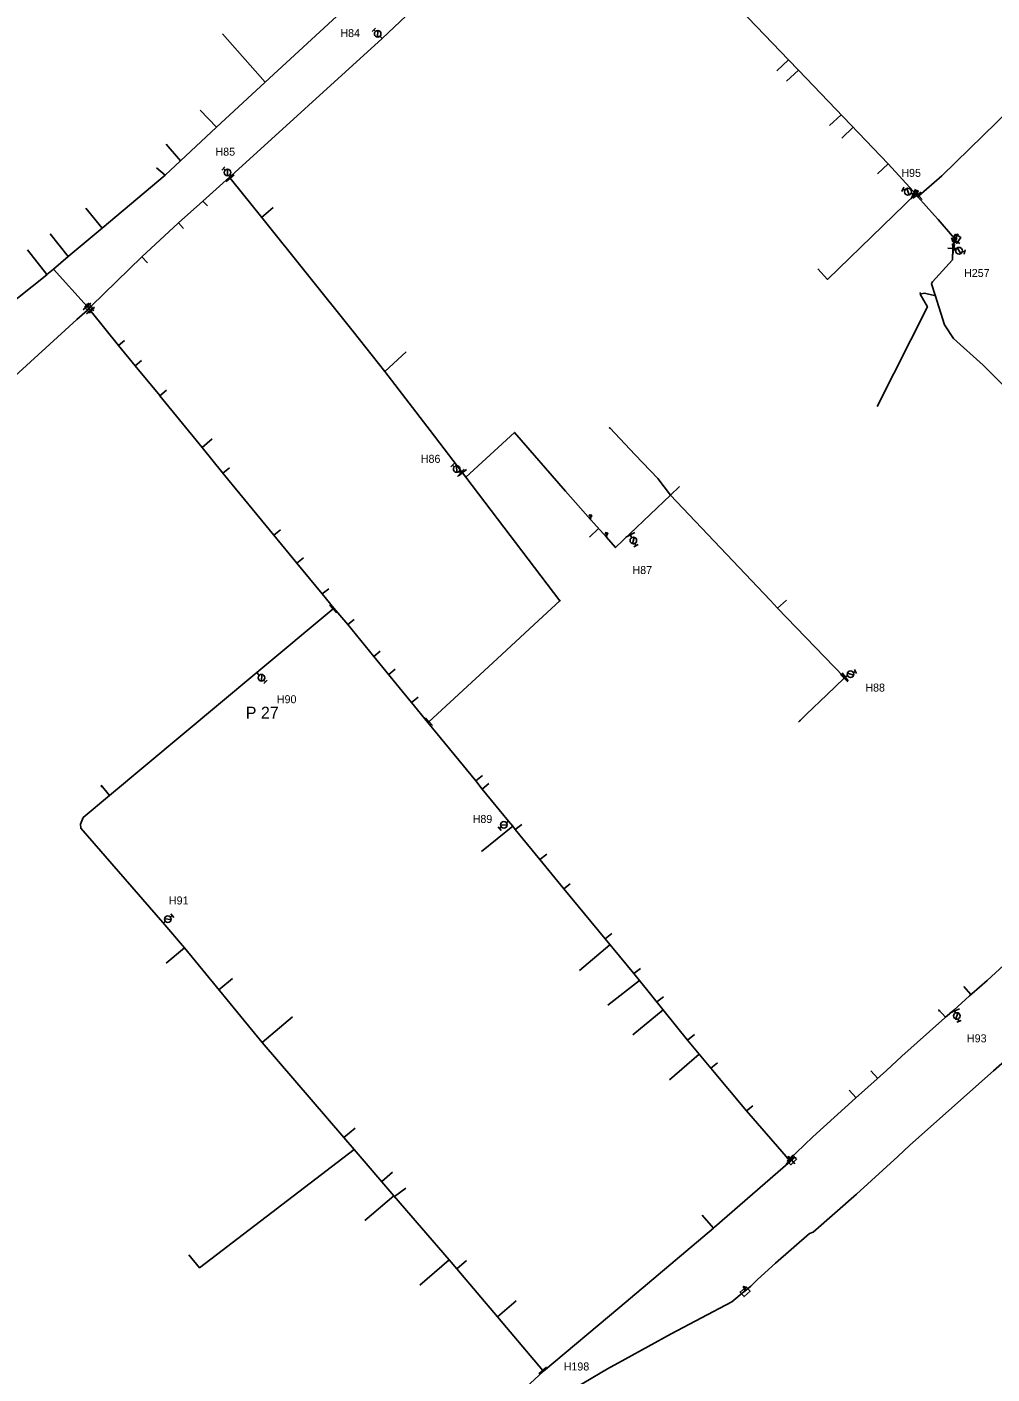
# Model space of a CAD drawing. Extents: x -548873 to -538270, y -1201997 to -1192514.
# Drawn here: x -544932.6 to -544691.4, y -1193789.4 to -1193452.8 of the extents above; entities that cross this region are included whole.
import ezdxf

# ---------------------------------------------------------------- set-up
doc = ezdxf.new("R2010")
doc.units = 0
for name, color, linetype in [('KN_HRAN_STÁTNÍ', 7, 'Continuous'), ('KN_PARC_Č', 7, 'Continuous'), ('KN_VKP_HRAN_SPORNÁ', 7, 'Continuous'), ('PK_PARC_Čv', 7, 'Continuous'), ('Vrstva 29', 7, 'Continuous'), ('Vrstva 39', 7, 'Continuous')]:
    doc.layers.add(name, color=color, linetype=linetype)

# ---------------------------------------------------------------- blocks, each defined once
blk = doc.blocks.new('160')
at = {"layer": 'KN_HRAN_STÁTNÍ'}
blk.add_circle((0, 0), 0.0458, dxfattribs=at)
blk = doc.blocks.new('147')
at = {"layer": 'KN_HRAN_STÁTNÍ'}
blk.add_line((0, 1.27), (0, -1.27), dxfattribs=at)
blk = doc.blocks.new('133')
at = {"layer": 'KN_HRAN_STÁTNÍ'}
for p, q in [((0.28, 0), (0, 0)), ((0.54, 0.58), (1.7, -0.58)), ((1.94, 0), (2.52, 0)), ((2.52, 0.58), (2.52, -0.58))]:
    blk.add_line(p, q, dxfattribs=at)
blk.add_circle((1.11, 0), 0.825, dxfattribs=at)
blk = doc.blocks.new('150')
at = {"layer": 'KN_HRAN_STÁTNÍ'}
blk.add_line((0, 1.27), (0, -1.27), dxfattribs=at)
blk = doc.blocks.new('123')
at = {"layer": 'KN_HRAN_STÁTNÍ'}
for p, q in [((-0.26, 0.96), (0.26, 0.96)), ((-0.19, 1.13), (0.19, 0.79)), ((-0.19, 0.79), (0, 0.96)), ((0, 1.22), (0, 0.96)), ((0, 0.96), (0.19, 1.13)), ((0, 0.96), (0, 0))]:
    blk.add_line(p, q, dxfattribs=at)
blk = doc.blocks.new('128')
at = {"layer": 'KN_HRAN_STÁTNÍ'}
for p, q in [((-0.19, 1.06), (-0.43, 1.15)), ((-0.36, 0.84), (-0.19, 1.06)), ((-0.19, 1.06), (-0.02, 1.25)), ((-0.19, 1.06), (0, 0)), ((0.05, 0.95), (-0.19, 1.06)), ((-0.1, 1), (0.41, 0.91)), ((-0.07, 0.82), (0.17, 0.96)), ((0.17, 0.96), (-0.02, 1.13)), ((0.17, 0.96), (0, 0)), ((0.19, 1.21), (0.17, 0.96)), ((0.17, 0.96), (0.38, 1.08)), ((0.36, 0.77), (0.17, 0.96))]:
    blk.add_line(p, q, dxfattribs=at)

msp = doc.modelspace()

# ---------------------------------------------------------------- linework, layer by layer
at = {"layer": 'KN_PARC_Č'}
for points in [[(-544873.033, -1193466.619), (-544883.731, -1193454.497)], [(-544742.227, -1193461.065), (-544745.196, -1193463.789)], [(-544739.778, -1193463.618), (-544742.725, -1193466.361)], [(-544885.192, -1193477.869), (-544889.335, -1193473.618)], [(-544729.091, -1193474.746), (-544732.034, -1193477.424)], [(-544726.1, -1193477.86), (-544728.929, -1193480.577)], [(-544894.197, -1193486.235), (-544897.8, -1193482.11)], [(-544898.064, -1193489.828), (-544900.243, -1193487.976)], [(-544717.339, -1193486.981), (-544720.032, -1193489.471)], [(-544888.647, -1193496.321), (-544887.5, -1193497.53)], [(-544710.407, -1193494.519), (-544732.514, -1193515.885), (-544734.919, -1193513.238)], [(-544913.832, -1193503.099), (-544917.852, -1193498.09)], [(-544873.952, -1193500.379), (-544871.054, -1193497.935)], [(-544894.752, -1193501.782), (-544893.436, -1193503.148)], [(-544922.268, -1193510.197), (-544926.82, -1193504.522)], [(-544927.61, -1193514.691), (-544932.433, -1193508.509)], [(-544903.885, -1193510.255), (-544902.488, -1193511.732)], [(-544709.33, -1193519.55), (-544707.512, -1193522.725), (-544720.054, -1193547.602)], [(-544705.585, -1193519.832), (-544705.74, -1193519.88), (-544707.62, -1193519.48), (-544708.22, -1193519.35), (-544709.33, -1193519.55)], [(-544709.228, -1193519.532), (-544709.322, -1193519.134)], [(-544909.698, -1193532.358), (-544908.188, -1193531.174)], [(-544905.517, -1193537.473), (-544903.967, -1193536.169)], [(-544843.108, -1193538.914), (-544837.816, -1193533.992)], [(-544899.413, -1193544.942), (-544897.761, -1193543.581)], [(-544888.849, -1193557.868), (-544886.29, -1193555.721)], [(-544883.617, -1193564.271), (-544881.968, -1193562.946)], [(-544771.738, -1193569.762), (-544769.5, -1193567.65)], [(-544870.88, -1193579.796), (-544869.263, -1193578.46)], [(-544789.711, -1193578.09), (-544791.978, -1193580.241)], [(-544865.131, -1193586.804), (-544863.448, -1193585.479)], [(-544858.846, -1193594.464), (-544857.155, -1193593.169)], [(-544744.998, -1193597.978), (-544742.759, -1193595.984)], [(-544852.38, -1193602.073), (-544850.854, -1193600.827)], [(-544845.888, -1193610.063), (-544844.277, -1193608.781)], [(-544842.178, -1193614.626), (-544840.545, -1193613.298)], [(-544836.52, -1193621.593), (-544834.816, -1193620.23)], [(-544739.399, -1193626.149), (-544739.759, -1193626.496)], [(-544820.435, -1193641.185), (-544818.766, -1193639.836)], [(-544913.879, -1193642.507), (-544914.117, -1193642.691)], [(-544911.976, -1193644.837), (-544914.069, -1193642.275)], [(-544818.785, -1193643.205), (-544817.121, -1193641.843)], [(-544811.174, -1193652.518), (-544818.983, -1193658.775)], [(-544810.548, -1193653.281), (-544808.92, -1193652.054)], [(-544804.407, -1193660.773), (-544802.667, -1193659.443)], [(-544798.406, -1193668.095), (-544796.782, -1193666.903)], [(-544788.101, -1193680.666), (-544786.411, -1193679.28)], [(-544893.189, -1193682.912), (-544897.792, -1193686.739)], [(-544786.877, -1193682.134), (-544794.498, -1193688.515)], [(-544780.898, -1193689.308), (-544779.247, -1193687.998)], [(-544884.614, -1193693.379), (-544881.222, -1193690.515)], [(-544779.504, -1193691.04), (-544787.416, -1193697.165)], [(-544775.194, -1193696.376), (-544773.501, -1193695.099)], [(-544696.662, -1193694.566), (-544698.439, -1193692.575)], [(-544773.59, -1193698.363), (-544781.188, -1193704.621)], [(-544704.534, -1193698.512), (-544704.765, -1193698.703)], [(-544702.986, -1193700.221), (-544704.735, -1193698.289)], [(-544873.845, -1193706.525), (-544866.26, -1193700.154)], [(-544767.49, -1193705.915), (-544765.716, -1193704.49)], [(-544764.572, -1193709.412), (-544772.018, -1193715.812)], [(-544761.655, -1193712.908), (-544759.951, -1193711.581)], [(-544719.951, -1193715.483), (-544721.654, -1193713.596)], [(-544725.331, -1193720.353), (-544727.063, -1193718.452)], [(-544752.717, -1193723.614), (-544751.169, -1193722.334)], [(-544853.421, -1193730.247), (-544850.57, -1193727.951)], [(-544850.798, -1193733.293), (-544889.439, -1193762.797), (-544892.119, -1193759.553)], [(-544843.94, -1193741.259), (-544841.239, -1193738.946)], [(-544840.872, -1193744.822), (-544848.147, -1193751.016)], [(-544840.715, -1193745.004), (-544837.908, -1193742.918)], [(-544761.018, -1193752.882), (-544763.857, -1193749.62)], [(-544827.064, -1193760.838), (-544834.422, -1193767.118)], [(-544825.186, -1193763.054), (-544822.763, -1193761.008)], [(-544815.004, -1193775.064), (-544810.343, -1193771.023)]]:
    msp.add_lwpolyline(points, dxfattribs=at)
at = {"layer": 'KN_VKP_HRAN_SPORNÁ'}
for points in [[(-544925.975, -1193513.316), (-544922.268, -1193510.197), (-544913.832, -1193503.099), (-544898.092, -1193489.854), (-544898.064, -1193489.828), (-544894.197, -1193486.235), (-544885.192, -1193477.869), (-544873.034, -1193466.62), (-544842.561, -1193438.428), (-544812.835, -1193411.457), (-544812.726, -1193411.357), (-544800.327, -1193400.27), (-544799.558, -1193390.689), (-544799.344, -1193382.742), (-544799.63, -1193373.727)], [(-544618.32, -1193373.547), (-544618.82, -1193374.46), (-544619.09, -1193374.97), (-544620.49, -1193377.221), (-544637.21, -1193404.11), (-544643.44, -1193413.61), (-544645.44, -1193416.9), (-544646.687, -1193418.924), (-544662.3, -1193444.264), (-544665.07, -1193448.54), (-544670.89, -1193456.94), (-544680.37, -1193467.03), (-544684.479, -1193471.289), (-544686.79, -1193473.29), (-544703.94, -1193490), (-544709.66, -1193495.02)], [(-544793.743, -1193408.084), (-544778.557, -1193423.289), (-544776.054, -1193425.797), (-544750.274, -1193452.675), (-544742.226, -1193461.066), (-544739.778, -1193463.618), (-544717.339, -1193486.981), (-544710.13, -1193494.82)], [(-544881.976, -1193490.354), (-544881.575, -1193489.989), (-544843.851, -1193455.663), (-544831.902, -1193444.36), (-544830.172, -1193442.723), (-544830.065, -1193442.622), (-544823.294, -1193436.106)], [(-544916.82, -1193522.85), (-544916.573, -1193522.589), (-544903.885, -1193510.255), (-544894.775, -1193501.803), (-544894.752, -1193501.782), (-544888.647, -1193496.321), (-544881.976, -1193490.354)], [(-544881.976, -1193490.354), (-544881.788, -1193490.589)], [(-544881.788, -1193490.589), (-544881.479, -1193490.969), (-544873.919, -1193500.42), (-544851.103, -1193528.925), (-544843.108, -1193538.914), (-544831.823, -1193553.642), (-544823.738, -1193564.193)], [(-544710.13, -1193494.82), (-544709.904, -1193495.234)], [(-544709.904, -1193495.234), (-544709.66, -1193495.02)], [(-544709.904, -1193495.234), (-544709.89, -1193495.26), (-544705.72, -1193499.91), (-544704.841, -1193500.925), (-544701.231, -1193505.09), (-544700.53, -1193505.56)], [(-544700.52, -1193506.23), (-544700.847, -1193506.756), (-544701.16, -1193507.68), (-544701.17, -1193508.11)], [(-544700.53, -1193505.56), (-544700.23, -1193505.79)], [(-544700.23, -1193505.79), (-544700.52, -1193506.23)], [(-544701.17, -1193508.11), (-544701.29, -1193511), (-544706.24, -1193516.53), (-544706.43, -1193516.76), (-544706.47, -1193517), (-544705.585, -1193519.832), (-544703.27, -1193527.24), (-544700.98, -1193530.67), (-544693.61, -1193537.3), (-544680.95, -1193549.85)], [(-544954.743, -1193539), (-544954.598, -1193538.861), (-544938.639, -1193523.522), (-544927.643, -1193514.719), (-544927.61, -1193514.691), (-544925.975, -1193513.316)], [(-544917.576, -1193522.658), (-544925.975, -1193513.316)], [(-545065.203, -1193622.374), (-545052.13, -1193618.053), (-545037.812, -1193613.321), (-545003.877, -1193595.413), (-544988.151, -1193585.243), (-544974.889, -1193574.667), (-544966.191, -1193567.738), (-544949.232, -1193552.353), (-544920.109, -1193525.934), (-544917.513, -1193523.579), (-544917.12, -1193523.165)], [(-544917.12, -1193523.165), (-544917.576, -1193522.658)], [(-544917.12, -1193523.165), (-544916.82, -1193522.85)], [(-544917.12, -1193523.165), (-544916.721, -1193523.66)], [(-544916.721, -1193523.66), (-544916.532, -1193523.893), (-544909.698, -1193532.358), (-544905.519, -1193537.471), (-544899.432, -1193544.919), (-544899.413, -1193544.942), (-544888.849, -1193557.868), (-544883.618, -1193564.27), (-544870.878, -1193579.798), (-544865.131, -1193586.804), (-544858.848, -1193594.462), (-544855.904, -1193598.05)], [(-544822.922, -1193565.264), (-544810.763, -1193554.122), (-544798.028, -1193568.777), (-544791.72, -1193575.862)], [(-544786.918, -1193552.98), (-544780.541, -1193559.694), (-544774.94, -1193565.591), (-544771.738, -1193569.762)], [(-544823.738, -1193564.193), (-544822.922, -1193565.264)], [(-544799.371, -1193596.16), (-544822.922, -1193565.264)], [(-544771.738, -1193569.762), (-544781.914, -1193579.452), (-544785.505, -1193582.872), (-544787.702, -1193580.318)], [(-544771.738, -1193569.762), (-544746.821, -1193596.054), (-544744.998, -1193597.978), (-544730.897, -1193612.601), (-544728.226, -1193615.37), (-544728.347, -1193615.501)], [(-544791.72, -1193575.862), (-544787.702, -1193580.318)], [(-544832.141, -1193626.382), (-544815.095, -1193610.661), (-544805.826, -1193602.113), (-544799.371, -1193596.16)], [(-544856.096, -1193598.21), (-544875.146, -1193614.106), (-544884.752, -1193622.121), (-544911.976, -1193644.837), (-544918.588, -1193650.354), (-544919.246, -1193652.011), (-544919.103, -1193653.018), (-544898.673, -1193676.585), (-544893.189, -1193682.912), (-544873.845, -1193706.525), (-544853.421, -1193730.247), (-544850.798, -1193733.293), (-544840.872, -1193744.822), (-544827.064, -1193760.838), (-544825.186, -1193763.054), (-544815.004, -1193775.064), (-544803.674, -1193788.427)], [(-544855.904, -1193598.05), (-544856.096, -1193598.21)], [(-544855.904, -1193598.05), (-544852.378, -1193602.075), (-544845.888, -1193610.063), (-544838.816, -1193618.76), (-544836.521, -1193621.592), (-544832.362, -1193626.585)], [(-544728.347, -1193615.501), (-544732.677, -1193619.673), (-544737.703, -1193624.515), (-544739.197, -1193625.955), (-544739.399, -1193626.149)], [(-544832.362, -1193626.585), (-544832.141, -1193626.382)], [(-544832.362, -1193626.585), (-544820.437, -1193641.183), (-544818.784, -1193643.206), (-544812.245, -1193651.212), (-544811.176, -1193652.515), (-544810.548, -1193653.281), (-544804.406, -1193660.775), (-544798.404, -1193668.097), (-544788.099, -1193680.668), (-544780.898, -1193689.308), (-544779.504, -1193691.04), (-544767.49, -1193705.915), (-544761.655, -1193712.909), (-544752.717, -1193723.614), (-544742.205, -1193735.678), (-544741.982, -1193735.892)], [(-544686.327, -1193685.256), (-544692.588, -1193691.012), (-544696.41, -1193694.34), (-544696.99, -1193694.86), (-544700.93, -1193698.48), (-544702.96, -1193700.19), (-544703.14, -1193700.4), (-544713.921, -1193709.981), (-544717.76, -1193713.5), (-544725.46, -1193720.47), (-544736.16, -1193730.06), (-544740.35, -1193734.13), (-544740.89, -1193734.66), (-544741.6, -1193735.29)], [(-544753.19, -1193768.67), (-544752.199, -1193767.805), (-544751.7, -1193767.37), (-544749.99, -1193765.72), (-544745.49, -1193761.67), (-544736.98, -1193754.24), (-544736.11, -1193753.94), (-544725.23, -1193744.44), (-544714.9, -1193735.03), (-544711.92, -1193732.21), (-544691.02, -1193713.6), (-544680.67, -1193704.51), (-544679.98, -1193703.76), (-544679.27, -1193702.36), (-544678.562, -1193701.598)], [(-544741.6, -1193735.29), (-544741.24, -1193735.709)], [(-544741.466, -1193735.906), (-544741.24, -1193735.709)], [(-544741.24, -1193735.709), (-544741.051, -1193735.545)], [(-544741.73, -1193736.135), (-544760.729, -1193752.634), (-544760.93, -1193752.808), (-544761.018, -1193752.882), (-544784.43, -1193772.606), (-544803.48, -1193788.656)], [(-544741.982, -1193735.892), (-544741.73, -1193736.135)], [(-544741.73, -1193736.135), (-544741.466, -1193735.906)], [(-544818.462, -1193813.455), (-544817.886, -1193812.916), (-544795.275, -1193792.673), (-544787.528, -1193788.017), (-544783.111, -1193785.609), (-544771.592, -1193779.33), (-544756.443, -1193771.342), (-544753.287, -1193768.749), (-544753.19, -1193768.67)], [(-544803.48, -1193788.656), (-544832.8, -1193815.665), (-544842.513, -1193824.613), (-544845.213, -1193827.1), (-544854.51, -1193834.908), (-544866.558, -1193845.027), (-544867.737, -1193846.021), (-544882.866, -1193860.53), (-544900.46, -1193875.864)], [(-544803.674, -1193788.427), (-544803.48, -1193788.656)]]:
    msp.add_lwpolyline(points, dxfattribs=at)
at = {"layer": 'PK_PARC_Čv'}
for points in [[(-544843.851, -1193455.663), (-544844.168, -1193455.335)], [(-544881.576, -1193489.99), (-544881.66, -1193489.91)], [(-544710.651, -1193494.755), (-544710.749, -1193494.653), (-544711.06, -1193494.54), (-544711.33, -1193494.44)], [(-544700.46, -1193504.59), (-544699.2, -1193505.42), (-544700.14, -1193506.87), (-544701.4, -1193506.04), (-544700.46, -1193504.59)], [(-544701.182, -1193508.409), (-544700.96, -1193508.42), (-544700.71, -1193508.47)], [(-544918.195, -1193522.847), (-544917.255, -1193521.857), (-544915.94, -1193523.27), (-544916.88, -1193524.26), (-544918.195, -1193522.847)], [(-544823.735, -1193564.197), (-544823.934, -1193564.428), (-544824.38, -1193564.01)], [(-544781.914, -1193579.453), (-544781.78, -1193579.714), (-544781.549, -1193580.162)], [(-544875.146, -1193614.106), (-544874.71, -1193614.578)], [(-544728.468, -1193615.618), (-544728.055, -1193615.184), (-544727.742, -1193615.038)], [(-544812.243, -1193651.214), (-544812.547, -1193651.462)], [(-544898.563, -1193676.712), (-544898.22, -1193676.432)], [(-544700.859, -1193698.414), (-544700.69, -1193698.61), (-544700.59, -1193698.87)], [(-544742.55, -1193736.09), (-544741.14, -1193734.71), (-544740.22, -1193735.67), (-544741.63, -1193737.05), (-544742.55, -1193736.09)], [(-544752.845, -1193767.546), (-544751.855, -1193768.673), (-544753.357, -1193769.993), (-544754.347, -1193768.866), (-544752.845, -1193767.546)]]:
    msp.add_lwpolyline(points, dxfattribs=at)

# ---------------------------------------------------------------- block references
for name, p, xscale, yscale, rotation in [('133', (-544844.168, -1193455.335), 1.0000000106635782, 1.0000000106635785, 134.00000165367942), ('133', (-544881.66, -1193489.91), 1.00000000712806, 1.00000000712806, 136.99999943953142), ('133', (-544711.33, -1193494.44), 1.0296949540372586, 1.0296949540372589, 155.86620948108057), ('150', (-544711.06, -1193494.54), 1.0296949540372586, 1.0296949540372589, -24.133790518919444), ('150', (-544700.96, -1193508.42), 1.0098116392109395, 1.0098116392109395, -10.610301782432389), ('133', (-544700.71, -1193508.47), 1.0060666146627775, 1.0060666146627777, -12.654735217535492), ('133', (-544824.38, -1193564.01), 1.00000000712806, 1.00000000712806, 136.99999943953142), ('150', (-544824.153, -1193564.223), 1.00000000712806, 1.00000000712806, 136.99999943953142), ('150', (-544781.78, -1193579.714), 0.9999999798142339, 0.9999999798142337, -61.99999866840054), ('133', (-544781.549, -1193580.162), 0.9999999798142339, 0.9999999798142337, -61.99999866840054), ('133', (-544874.71, -1193614.578), 1.00000000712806, 1.00000000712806, -46.99999943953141), ('150', (-544728.055, -1193615.184), 1.000000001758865, 1.000000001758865, 35.99999933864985), ('133', (-544727.742, -1193615.038), 1.0138865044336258, 1.0138865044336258, 27.56531359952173), ('133', (-544812.547, -1193651.462), 1.0000000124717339, 1.0000000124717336, -139.99999868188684), ('133', (-544898.22, -1193676.432), 1.0000000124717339, 1.0000000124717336, 40.00000131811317), ('150', (-544700.69, -1193698.61), 1.0000000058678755, 1.0000000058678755, -68.00000099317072), ('133', (-544700.59, -1193698.87), 1.0000000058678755, 1.0000000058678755, -68.00000099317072)]:
    msp.add_blockref(name, p, dxfattribs=dict(at, xscale=xscale, yscale=yscale, rotation=rotation))
at = {"layer": 'Vrstva 29'}
for name, p, xscale, yscale, rotation in [('147', (-544881.788, -1193490.589), 1.000000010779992, 1.0000000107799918, 128.99999891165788), ('160', (-544881.976, -1193490.354), 1.00000000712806, 1.00000000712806, -136.99999943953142), ('147', (-544710.13, -1193494.82), 1.000000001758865, 1.000000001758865, 125.99999933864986), ('147', (-544709.66, -1193495.02), 1.0000000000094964, 1.0000000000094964, -137.9999986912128), ('160', (-544709.904, -1193495.234), 0.9999999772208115, 0.9999999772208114, 79.99999971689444), ('147', (-544700.52, -1193506.23), 0.9999999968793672, 0.9999999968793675, -122.00000027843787), ('147', (-544700.53, -1193505.56), 1.000000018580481, 1.000000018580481, 144.99999976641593), ('160', (-544700.23, -1193505.79), 0.9999999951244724, 0.9999999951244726, -123.00000127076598), ('147', (-544701.17, -1193508.11), 1.000000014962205, 1.0000000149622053, -90.99999994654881), ('160', (-544925.975, -1193513.316), 1.0000000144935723, 1.0000000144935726, -139.00000089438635), ('147', (-544917.576, -1193522.658), 1.0000000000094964, 1.0000000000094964, 132.0000013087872), ('147', (-544916.82, -1193522.85), 1.00000000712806, 1.00000000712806, -133.00000056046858), ('147', (-544916.721, -1193523.66), 1.000000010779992, 1.0000000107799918, 128.99999891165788), ('160', (-544917.12, -1193523.165), 1.00000000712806, 1.00000000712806, -133.00000056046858), ('160', (-544786.918, -1193552.98), 1.0000000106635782, 1.0000000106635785, -45.99999834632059), ('147', (-544823.738, -1193564.193), 1.000000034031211, 1.0000000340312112, 128.00000040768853), ('160', (-544822.922, -1193565.264), 1.000000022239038, 1.0000000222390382, -94.99999998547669), ('160', (-544771.738, -1193569.762), 1.0000000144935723, 1.0000000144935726, -49.00000089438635), ('160', (-544791.72, -1193575.862), 1.0000000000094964, 1.0000000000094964, -47.99999869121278), ('160', (-544787.702, -1193580.318), 1.0000000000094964, 1.0000000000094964, -47.99999869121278), ('147', (-544856.096, -1193598.21), 1.0000000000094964, 1.0000000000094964, -137.9999986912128), ('160', (-544799.371, -1193596.16), 1.000000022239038, 1.0000000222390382, -94.99999998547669), ('160', (-544855.904, -1193598.05), 1.0000000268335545, 1.0000000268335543, 176.00000028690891), ('147', (-544728.347, -1193615.501), 1.0000000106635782, 1.0000000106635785, 45.99999834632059), ('147', (-544832.141, -1193626.382), 1.00000000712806, 1.00000000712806, -136.99999943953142), ('160', (-544832.362, -1193626.585), 1.0002788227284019, 1.0002788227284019, 176.70930040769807), ('160', (-544739.399, -1193626.149), 1.0000000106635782, 1.0000000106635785, -135.99999834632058), ('147', (-544741.6, -1193735.29), 0.9999999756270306, 0.9999999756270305, 86.99999998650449), ('147', (-544741.982, -1193735.892), 1.00000000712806, 1.00000000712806, 136.99999943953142), ('147', (-544741.466, -1193735.906), 1.0000000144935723, 1.0000000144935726, -139.00000089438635), ('160', (-544741.24, -1193735.709), 1.0000000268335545, 1.0000000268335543, 176.00000028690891), ('160', (-544741.051, -1193735.545), 1.0000000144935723, 1.0000000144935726, 40.99999910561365), ('160', (-544741.73, -1193736.135), 1.000000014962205, 1.0000000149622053, -90.99999994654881), ('160', (-544753.19, -1193768.67), 1.0000000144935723, 1.0000000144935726, -139.00000089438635), ('147', (-544803.674, -1193788.427), 1.0000000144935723, 1.0000000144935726, 130.99999910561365), ('160', (-544803.48, -1193788.656), 1.0000000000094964, 1.0000000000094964, -137.9999986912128)]:
    msp.add_blockref(name, p, dxfattribs=dict(at, xscale=xscale, yscale=yscale, rotation=rotation))
at = {"layer": 'Vrstva 39'}
for name, p in [('128', (-544710.13, -1193494.82)), ('123', (-544701.17, -1193508.11)), ('123', (-544700.23, -1193505.79)), ('128', (-544791.72, -1193575.862)), ('128', (-544787.702, -1193580.318)), ('128', (-544753.19, -1193768.67))]:
    msp.add_blockref(name, p, dxfattribs=at)

# ---------------------------------------------------------------- texts
at = {"layer": 'PK_PARC_Čv'}
for s, height, p in [('H84', 2, (-544854.268, -1193455.345)), ('H85', 2, (-544885.49, -1193484.98)), ('H95', 2, (-544714.04, -1193490.27)), ('H257', 2, (-544698.36, -1193515.28)), ('H86', 2, (-544834.16, -1193561.71)), ('H87', 2, (-544781.249, -1193589.492)), ('H88', 2, (-544723.042, -1193618.858)), ('H90', 2, (-544870.15, -1193621.768)), ('P 27', 3, (-544877.92, -1193625.638)), ('H89', 2, (-544821.197, -1193651.672)), ('H91', 2, (-544897.13, -1193672.042)), ('H93', 2, (-544697.64, -1193706.48)), ('H198', 2, (-544798.444, -1193788.462))]:
    msp.add_text(s, height=height, dxfattribs=at).set_placement(p)

doc.saveas('drawing.dxf')
